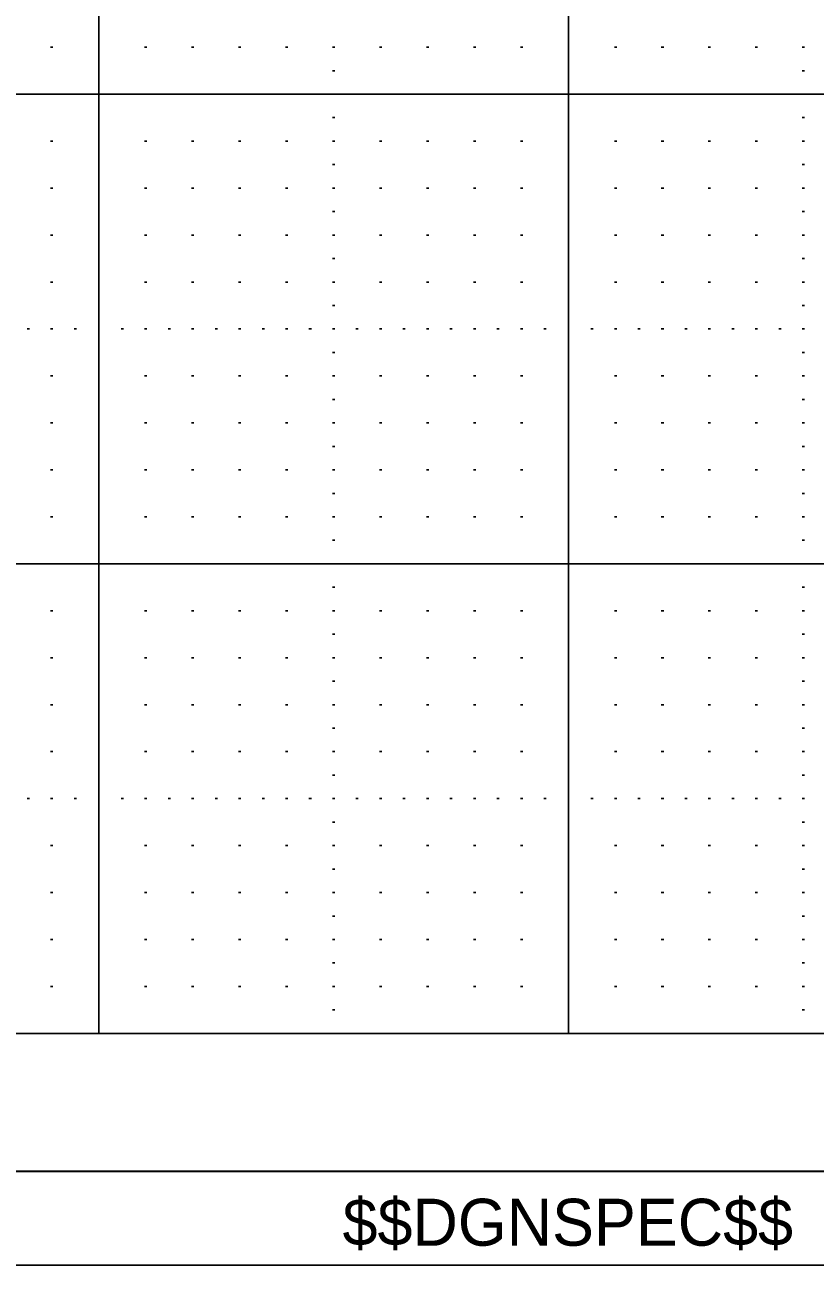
# Model space of a CAD drawing. Extents: x -1.3 to 32.1, y -0.2 to 20.7.
# Drawn here: x 25.588 to 27.27, y -0.2 to 2.441 of the extents above; entities that cross this region are included whole.
import ezdxf

# ---------------------------------------------------------------- set-up
doc = ezdxf.new("R2010")
doc.units = 0
for name, color, linetype in [('Level 1', 7, 'Continuous'), ('Level 37', 7, 'Continuous'), ('Level 48', 7, 'Continuous'), ('Level 5', 7, 'Continuous'), ('Level 6', 7, 'Continuous'), ('Level 62', 7, 'Continuous'), ('Level 63', 7, 'Continuous')]:
    doc.layers.add(name, color=color, linetype=linetype)

msp = doc.modelspace()

# ---------------------------------------------------------------- linework, layer by layer
at = {"layer": 'Level 1'}
msp.add_line((31.617, -0.001), (-0.001, -0.001), dxfattribs=at)
at = {"layer": 'Level 37'}
msp.add_line((31.618, -0.001), (-0.001, -0.001), dxfattribs=at)
at = {"layer": 'Level 5'}
for p, q in [((25.6425, 2.393), (25.6475, 2.393)), ((25.8425, 2.393), (25.8475, 2.393)), ((25.9425, 2.393), (25.9475, 2.393)), ((26.0425, 2.393), (26.0475, 2.393)), ((26.1425, 2.393), (26.1475, 2.393)), ((26.2425, 2.393), (26.2475, 2.393)), ((26.3425, 2.393), (26.3475, 2.393)), ((26.4425, 2.393), (26.4475, 2.393)), ((26.5425, 2.393), (26.5475, 2.393)), ((26.6425, 2.393), (26.6475, 2.393)), ((26.8425, 2.393), (26.8475, 2.393)), ((26.9425, 2.393), (26.9475, 2.393)), ((27.0425, 2.393), (27.0475, 2.393)), ((27.1425, 2.393), (27.1475, 2.393)), ((27.2425, 2.393), (27.2475, 2.393)), ((26.2425, 2.343), (26.2475, 2.343)), ((27.2425, 2.343), (27.2475, 2.343)), ((26.2425, 2.243), (26.2475, 2.243)), ((27.2425, 2.243), (27.2475, 2.243)), ((25.6425, 2.193), (25.6475, 2.193)), ((25.8425, 2.193), (25.8475, 2.193)), ((25.9425, 2.193), (25.9475, 2.193)), ((26.0425, 2.193), (26.0475, 2.193)), ((26.1425, 2.193), (26.1475, 2.193)), ((26.2425, 2.193), (26.2475, 2.193)), ((26.3425, 2.193), (26.3475, 2.193)), ((26.4425, 2.193), (26.4475, 2.193)), ((26.5425, 2.193), (26.5475, 2.193)), ((26.6425, 2.193), (26.6475, 2.193)), ((26.8425, 2.193), (26.8475, 2.193)), ((26.9425, 2.193), (26.9475, 2.193)), ((27.0425, 2.193), (27.0475, 2.193)), ((27.1425, 2.193), (27.1475, 2.193)), ((27.2425, 2.193), (27.2475, 2.193)), ((26.2425, 2.143), (26.2475, 2.143)), ((27.2425, 2.143), (27.2475, 2.143)), ((25.6425, 2.093), (25.6475, 2.093)), ((25.8425, 2.093), (25.8475, 2.093)), ((25.9425, 2.093), (25.9475, 2.093)), ((26.0425, 2.093), (26.0475, 2.093)), ((26.1425, 2.093), (26.1475, 2.093)), ((26.2425, 2.093), (26.2475, 2.093)), ((26.3425, 2.093), (26.3475, 2.093)), ((26.4425, 2.093), (26.4475, 2.093)), ((26.5425, 2.093), (26.5475, 2.093)), ((26.6425, 2.093), (26.6475, 2.093)), ((26.8425, 2.093), (26.8475, 2.093)), ((26.9425, 2.093), (26.9475, 2.093)), ((27.0425, 2.093), (27.0475, 2.093)), ((27.1425, 2.093), (27.1475, 2.093)), ((27.2425, 2.093), (27.2475, 2.093)), ((26.2425, 2.043), (26.2475, 2.043)), ((27.2425, 2.043), (27.2475, 2.043)), ((25.6425, 1.993), (25.6475, 1.993)), ((25.8425, 1.993), (25.8475, 1.993)), ((25.9425, 1.993), (25.9475, 1.993)), ((26.0425, 1.993), (26.0475, 1.993)), ((26.1425, 1.993), (26.1475, 1.993)), ((26.2425, 1.993), (26.2475, 1.993)), ((26.3425, 1.993), (26.3475, 1.993)), ((26.4425, 1.993), (26.4475, 1.993)), ((26.5425, 1.993), (26.5475, 1.993)), ((26.6425, 1.993), (26.6475, 1.993)), ((26.8425, 1.993), (26.8475, 1.993)), ((26.9425, 1.993), (26.9475, 1.993)), ((27.0425, 1.993), (27.0475, 1.993)), ((27.1425, 1.993), (27.1475, 1.993)), ((27.2425, 1.993), (27.2475, 1.993)), ((26.2425, 1.943), (26.2475, 1.943)), ((27.2425, 1.943), (27.2475, 1.943)), ((25.6425, 1.893), (25.6475, 1.893)), ((25.8425, 1.893), (25.8475, 1.893)), ((25.9425, 1.893), (25.9475, 1.893)), ((26.0425, 1.893), (26.0475, 1.893)), ((26.1425, 1.893), (26.1475, 1.893)), ((26.2425, 1.893), (26.2475, 1.893)), ((26.3425, 1.893), (26.3475, 1.893)), ((26.4425, 1.893), (26.4475, 1.893)), ((26.5425, 1.893), (26.5475, 1.893)), ((26.6425, 1.893), (26.6475, 1.893)), ((26.8425, 1.893), (26.8475, 1.893)), ((26.9425, 1.893), (26.9475, 1.893)), ((27.0425, 1.893), (27.0475, 1.893)), ((27.1425, 1.893), (27.1475, 1.893)), ((27.2425, 1.893), (27.2475, 1.893)), ((26.2425, 1.843), (26.2475, 1.843)), ((27.2425, 1.843), (27.2475, 1.843)), ((25.5925, 1.793), (25.5975, 1.793)), ((25.6425, 1.793), (25.6475, 1.793)), ((25.6925, 1.793), (25.6975, 1.793)), ((25.7925, 1.793), (25.7975, 1.793)), ((25.8425, 1.793), (25.8475, 1.793)), ((25.8925, 1.793), (25.8975, 1.793)), ((25.9425, 1.793), (25.9475, 1.793)), ((25.9925, 1.793), (25.9975, 1.793)), ((26.0425, 1.793), (26.0475, 1.793)), ((26.0925, 1.793), (26.0975, 1.793)), ((26.1425, 1.793), (26.1475, 1.793)), ((26.1925, 1.793), (26.1975, 1.793)), ((26.2425, 1.793), (26.2475, 1.793)), ((26.2925, 1.793), (26.2975, 1.793)), ((26.3425, 1.793), (26.3475, 1.793)), ((26.3925, 1.793), (26.3975, 1.793)), ((26.4425, 1.793), (26.4475, 1.793)), ((26.4925, 1.793), (26.4975, 1.793)), ((26.5425, 1.793), (26.5475, 1.793)), ((26.5925, 1.793), (26.5975, 1.793)), ((26.6425, 1.793), (26.6475, 1.793)), ((26.6925, 1.793), (26.6975, 1.793)), ((26.7925, 1.793), (26.7975, 1.793)), ((26.8425, 1.793), (26.8475, 1.793)), ((26.8925, 1.793), (26.8975, 1.793)), ((26.9425, 1.793), (26.9475, 1.793)), ((26.9925, 1.793), (26.9975, 1.793)), ((27.0425, 1.793), (27.0475, 1.793)), ((27.0925, 1.793), (27.0975, 1.793)), ((27.1425, 1.793), (27.1475, 1.793)), ((27.1925, 1.793), (27.1975, 1.793)), ((27.2425, 1.793), (27.2475, 1.793)), ((26.2425, 1.743), (26.2475, 1.743)), ((27.2425, 1.743), (27.2475, 1.743)), ((25.6425, 1.693), (25.6475, 1.693)), ((25.8425, 1.693), (25.8475, 1.693)), ((25.9425, 1.693), (25.9475, 1.693)), ((26.0425, 1.693), (26.0475, 1.693)), ((26.1425, 1.693), (26.1475, 1.693)), ((26.2425, 1.693), (26.2475, 1.693)), ((26.3425, 1.693), (26.3475, 1.693)), ((26.4425, 1.693), (26.4475, 1.693)), ((26.5425, 1.693), (26.5475, 1.693)), ((26.6425, 1.693), (26.6475, 1.693)), ((26.8425, 1.693), (26.8475, 1.693)), ((26.9425, 1.693), (26.9475, 1.693)), ((27.0425, 1.693), (27.0475, 1.693)), ((27.1425, 1.693), (27.1475, 1.693)), ((27.2425, 1.693), (27.2475, 1.693)), ((26.2425, 1.643), (26.2475, 1.643)), ((27.2425, 1.643), (27.2475, 1.643)), ((25.6425, 1.593), (25.6475, 1.593)), ((25.8425, 1.593), (25.8475, 1.593)), ((25.9425, 1.593), (25.9475, 1.593)), ((26.0425, 1.593), (26.0475, 1.593)), ((26.1425, 1.593), (26.1475, 1.593)), ((26.2425, 1.593), (26.2475, 1.593)), ((26.3425, 1.593), (26.3475, 1.593)), ((26.4425, 1.593), (26.4475, 1.593)), ((26.5425, 1.593), (26.5475, 1.593)), ((26.6425, 1.593), (26.6475, 1.593)), ((26.8425, 1.593), (26.8475, 1.593)), ((26.9425, 1.593), (26.9475, 1.593)), ((27.0425, 1.593), (27.0475, 1.593)), ((27.1425, 1.593), (27.1475, 1.593)), ((27.2425, 1.593), (27.2475, 1.593)), ((26.2425, 1.543), (26.2475, 1.543)), ((27.2425, 1.543), (27.2475, 1.543)), ((25.6425, 1.493), (25.6475, 1.493)), ((25.8425, 1.493), (25.8475, 1.493)), ((25.9425, 1.493), (25.9475, 1.493)), ((26.0425, 1.493), (26.0475, 1.493)), ((26.1425, 1.493), (26.1475, 1.493)), ((26.2425, 1.493), (26.2475, 1.493)), ((26.3425, 1.493), (26.3475, 1.493)), ((26.4425, 1.493), (26.4475, 1.493)), ((26.5425, 1.493), (26.5475, 1.493)), ((26.6425, 1.493), (26.6475, 1.493)), ((26.8425, 1.493), (26.8475, 1.493)), ((26.9425, 1.493), (26.9475, 1.493)), ((27.0425, 1.493), (27.0475, 1.493)), ((27.1425, 1.493), (27.1475, 1.493)), ((27.2425, 1.493), (27.2475, 1.493)), ((26.2425, 1.443), (26.2475, 1.443)), ((27.2425, 1.443), (27.2475, 1.443)), ((25.6425, 1.393), (25.6475, 1.393)), ((25.8425, 1.393), (25.8475, 1.393)), ((25.9425, 1.393), (25.9475, 1.393)), ((26.0425, 1.393), (26.0475, 1.393)), ((26.1425, 1.393), (26.1475, 1.393)), ((26.2425, 1.393), (26.2475, 1.393)), ((26.3425, 1.393), (26.3475, 1.393)), ((26.4425, 1.393), (26.4475, 1.393)), ((26.5425, 1.393), (26.5475, 1.393)), ((26.6425, 1.393), (26.6475, 1.393)), ((26.8425, 1.393), (26.8475, 1.393)), ((26.9425, 1.393), (26.9475, 1.393)), ((27.0425, 1.393), (27.0475, 1.393)), ((27.1425, 1.393), (27.1475, 1.393)), ((27.2425, 1.393), (27.2475, 1.393)), ((26.2425, 1.343), (26.2475, 1.343)), ((27.2425, 1.343), (27.2475, 1.343)), ((26.2425, 1.243), (26.2475, 1.243)), ((27.2425, 1.243), (27.2475, 1.243)), ((25.6425, 1.193), (25.6475, 1.193)), ((25.8425, 1.193), (25.8475, 1.193)), ((25.9425, 1.193), (25.9475, 1.193)), ((26.0425, 1.193), (26.0475, 1.193)), ((26.1425, 1.193), (26.1475, 1.193)), ((26.2425, 1.193), (26.2475, 1.193)), ((26.3425, 1.193), (26.3475, 1.193)), ((26.4425, 1.193), (26.4475, 1.193)), ((26.5425, 1.193), (26.5475, 1.193)), ((26.6425, 1.193), (26.6475, 1.193)), ((26.8425, 1.193), (26.8475, 1.193)), ((26.9425, 1.193), (26.9475, 1.193)), ((27.0425, 1.193), (27.0475, 1.193)), ((27.1425, 1.193), (27.1475, 1.193)), ((27.2425, 1.193), (27.2475, 1.193)), ((26.2425, 1.143), (26.2475, 1.143)), ((27.2425, 1.143), (27.2475, 1.143)), ((25.6425, 1.093), (25.6475, 1.093)), ((25.8425, 1.093), (25.8475, 1.093)), ((25.9425, 1.093), (25.9475, 1.093)), ((26.0425, 1.093), (26.0475, 1.093)), ((26.1425, 1.093), (26.1475, 1.093)), ((26.2425, 1.093), (26.2475, 1.093)), ((26.3425, 1.093), (26.3475, 1.093)), ((26.4425, 1.093), (26.4475, 1.093)), ((26.5425, 1.093), (26.5475, 1.093)), ((26.6425, 1.093), (26.6475, 1.093)), ((26.8425, 1.093), (26.8475, 1.093)), ((26.9425, 1.093), (26.9475, 1.093)), ((27.0425, 1.093), (27.0475, 1.093)), ((27.1425, 1.093), (27.1475, 1.093)), ((27.2425, 1.093), (27.2475, 1.093)), ((26.2425, 1.043), (26.2475, 1.043)), ((27.2425, 1.043), (27.2475, 1.043)), ((25.6425, 0.993), (25.6475, 0.993)), ((25.8425, 0.993), (25.8475, 0.993)), ((25.9425, 0.993), (25.9475, 0.993)), ((26.0425, 0.993), (26.0475, 0.993)), ((26.1425, 0.993), (26.1475, 0.993)), ((26.2425, 0.993), (26.2475, 0.993)), ((26.3425, 0.993), (26.3475, 0.993)), ((26.4425, 0.993), (26.4475, 0.993)), ((26.5425, 0.993), (26.5475, 0.993)), ((26.6425, 0.993), (26.6475, 0.993)), ((26.8425, 0.993), (26.8475, 0.993)), ((26.9425, 0.993), (26.9475, 0.993)), ((27.0425, 0.993), (27.0475, 0.993)), ((27.1425, 0.993), (27.1475, 0.993)), ((27.2425, 0.993), (27.2475, 0.993)), ((26.2425, 0.943), (26.2475, 0.943)), ((27.2425, 0.943), (27.2475, 0.943)), ((25.6425, 0.893), (25.6475, 0.893)), ((25.8425, 0.893), (25.8475, 0.893)), ((25.9425, 0.893), (25.9475, 0.893)), ((26.0425, 0.893), (26.0475, 0.893)), ((26.1425, 0.893), (26.1475, 0.893)), ((26.2425, 0.893), (26.2475, 0.893)), ((26.3425, 0.893), (26.3475, 0.893)), ((26.4425, 0.893), (26.4475, 0.893)), ((26.5425, 0.893), (26.5475, 0.893)), ((26.6425, 0.893), (26.6475, 0.893)), ((26.8425, 0.893), (26.8475, 0.893)), ((26.9425, 0.893), (26.9475, 0.893)), ((27.0425, 0.893), (27.0475, 0.893)), ((27.1425, 0.893), (27.1475, 0.893)), ((27.2425, 0.893), (27.2475, 0.893)), ((26.2425, 0.843), (26.2475, 0.843)), ((27.2425, 0.843), (27.2475, 0.843)), ((25.5925, 0.793), (25.5975, 0.793)), ((25.6425, 0.793), (25.6475, 0.793)), ((25.6925, 0.793), (25.6975, 0.793)), ((25.7925, 0.793), (25.7975, 0.793)), ((25.8425, 0.793), (25.8475, 0.793)), ((25.8925, 0.793), (25.8975, 0.793)), ((25.9425, 0.793), (25.9475, 0.793)), ((25.9925, 0.793), (25.9975, 0.793)), ((26.0425, 0.793), (26.0475, 0.793)), ((26.0925, 0.793), (26.0975, 0.793)), ((26.1425, 0.793), (26.1475, 0.793)), ((26.1925, 0.793), (26.1975, 0.793)), ((26.2425, 0.793), (26.2475, 0.793)), ((26.2925, 0.793), (26.2975, 0.793)), ((26.3425, 0.793), (26.3475, 0.793)), ((26.3925, 0.793), (26.3975, 0.793)), ((26.4425, 0.793), (26.4475, 0.793)), ((26.4925, 0.793), (26.4975, 0.793)), ((26.5425, 0.793), (26.5475, 0.793)), ((26.5925, 0.793), (26.5975, 0.793)), ((26.6425, 0.793), (26.6475, 0.793)), ((26.6925, 0.793), (26.6975, 0.793)), ((26.7925, 0.793), (26.7975, 0.793)), ((26.8425, 0.793), (26.8475, 0.793)), ((26.8925, 0.793), (26.8975, 0.793)), ((26.9425, 0.793), (26.9475, 0.793)), ((26.9925, 0.793), (26.9975, 0.793)), ((27.0425, 0.793), (27.0475, 0.793)), ((27.0925, 0.793), (27.0975, 0.793)), ((27.1425, 0.793), (27.1475, 0.793)), ((27.1925, 0.793), (27.1975, 0.793)), ((27.2425, 0.793), (27.2475, 0.793)), ((26.2425, 0.743), (26.2475, 0.743)), ((27.2425, 0.743), (27.2475, 0.743)), ((25.6425, 0.693), (25.6475, 0.693)), ((25.8425, 0.693), (25.8475, 0.693)), ((25.9425, 0.693), (25.9475, 0.693)), ((26.0425, 0.693), (26.0475, 0.693)), ((26.1425, 0.693), (26.1475, 0.693)), ((26.2425, 0.693), (26.2475, 0.693)), ((26.3425, 0.693), (26.3475, 0.693)), ((26.4425, 0.693), (26.4475, 0.693)), ((26.5425, 0.693), (26.5475, 0.693)), ((26.6425, 0.693), (26.6475, 0.693)), ((26.8425, 0.693), (26.8475, 0.693)), ((26.9425, 0.693), (26.9475, 0.693)), ((27.0425, 0.693), (27.0475, 0.693)), ((27.1425, 0.693), (27.1475, 0.693)), ((27.2425, 0.693), (27.2475, 0.693)), ((26.2425, 0.643), (26.2475, 0.643)), ((27.2425, 0.643), (27.2475, 0.643)), ((25.6425, 0.593), (25.6475, 0.593)), ((25.8425, 0.593), (25.8475, 0.593)), ((25.9425, 0.593), (25.9475, 0.593)), ((26.0425, 0.593), (26.0475, 0.593)), ((26.1425, 0.593), (26.1475, 0.593)), ((26.2425, 0.593), (26.2475, 0.593)), ((26.3425, 0.593), (26.3475, 0.593)), ((26.4425, 0.593), (26.4475, 0.593)), ((26.5425, 0.593), (26.5475, 0.593)), ((26.6425, 0.593), (26.6475, 0.593)), ((26.8425, 0.593), (26.8475, 0.593)), ((26.9425, 0.593), (26.9475, 0.593)), ((27.0425, 0.593), (27.0475, 0.593)), ((27.1425, 0.593), (27.1475, 0.593)), ((27.2425, 0.593), (27.2475, 0.593)), ((26.2425, 0.543), (26.2475, 0.543)), ((27.2425, 0.543), (27.2475, 0.543)), ((25.6425, 0.493), (25.6475, 0.493)), ((25.8425, 0.493), (25.8475, 0.493)), ((25.9425, 0.493), (25.9475, 0.493)), ((26.0425, 0.493), (26.0475, 0.493)), ((26.1425, 0.493), (26.1475, 0.493)), ((26.2425, 0.493), (26.2475, 0.493)), ((26.3425, 0.493), (26.3475, 0.493)), ((26.4425, 0.493), (26.4475, 0.493)), ((26.5425, 0.493), (26.5475, 0.493)), ((26.6425, 0.493), (26.6475, 0.493)), ((26.8425, 0.493), (26.8475, 0.493)), ((26.9425, 0.493), (26.9475, 0.493)), ((27.0425, 0.493), (27.0475, 0.493)), ((27.1425, 0.493), (27.1475, 0.493)), ((27.2425, 0.493), (27.2475, 0.493)), ((26.2425, 0.443), (26.2475, 0.443)), ((27.2425, 0.443), (27.2475, 0.443)), ((25.6425, 0.393), (25.6475, 0.393)), ((25.8425, 0.393), (25.8475, 0.393)), ((25.9425, 0.393), (25.9475, 0.393)), ((26.0425, 0.393), (26.0475, 0.393)), ((26.1425, 0.393), (26.1475, 0.393)), ((26.2425, 0.393), (26.2475, 0.393)), ((26.3425, 0.393), (26.3475, 0.393)), ((26.4425, 0.393), (26.4475, 0.393)), ((26.5425, 0.393), (26.5475, 0.393)), ((26.6425, 0.393), (26.6475, 0.393)), ((26.8425, 0.393), (26.8475, 0.393)), ((26.9425, 0.393), (26.9475, 0.393)), ((27.0425, 0.393), (27.0475, 0.393)), ((27.1425, 0.393), (27.1475, 0.393)), ((27.2425, 0.393), (27.2475, 0.393)), ((26.2425, 0.343), (26.2475, 0.343)), ((27.2425, 0.343), (27.2475, 0.343))]:
    msp.add_line(p, q, dxfattribs=at)
at = {"layer": 'Level 6'}
for p, q in [((25.745, 0.293), (25.745, 10.293)), ((26.745, 0.293), (26.745, 10.293)), ((31.617, 2.293), (-0.001, 2.293)), ((31.617, 1.293), (-0.001, 1.293)), ((31.617, 0.293), (-0.001, 0.293))]:
    msp.add_line(p, q, dxfattribs=at)
at = {"layer": 'Level 62'}
msp.add_line((-0.001, 0), (31.618, 0), dxfattribs=at)
at = {"layer": 'Level 63'}
msp.add_lwpolyline([(-1.263, -0.2005), (32.067, -0.2005), (32.067, 20.7465), (-1.263, 20.7465)], close=True, dxfattribs=at)

# ---------------------------------------------------------------- texts
at = {"layer": 'Level 48'}
msp.add_text('$$DGNSPEC$$', height=0.100002, dxfattribs=at).set_placement((26.264, -0.159))

doc.saveas('drawing.dxf')
